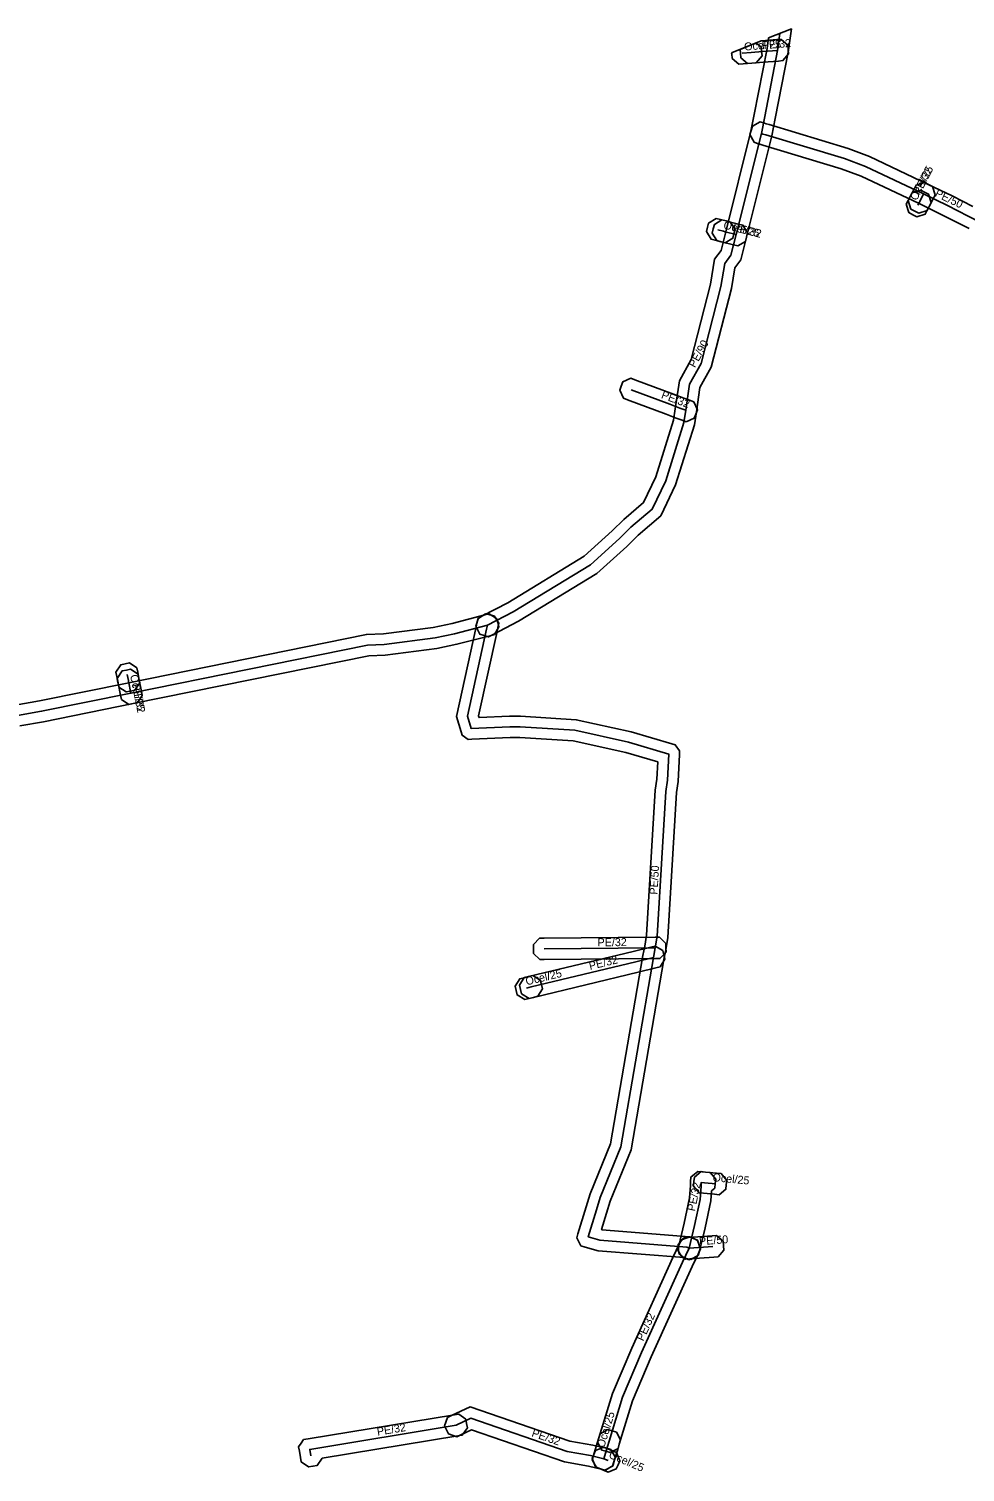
# Model space of a CAD drawing. Extents: x -677728 to -676939, y -1057290 to -1056960.
# Drawn here: x -677137.1 to -677049.4, y -1057099.7 to -1056964.4 of the extents above; entities that cross this region are included whole.
import ezdxf

# ---------------------------------------------------------------- set-up
doc = ezdxf.new("R2010")
doc.units = 0
for name, color, linetype in [('1', 7, 'Continuous'), ('24', 7, 'Continuous'), ('28', 7, 'Continuous'), ('30', 7, 'Continuous')]:
    doc.layers.add(name, color=color, linetype=linetype)

msp = doc.modelspace()

# ---------------------------------------------------------------- linework, layer by layer
at = {"layer": '1'}
for points in [[(-677067.91, -1056966.29), (-677067.77, -1056965.29), (-677065.63, -1056964.44), (-677065.93, -1056966.61), (-677067.15, -1056972.85), (-677067.46, -1056974.46), (-677069.84, -1056983.95), (-677070.38, -1056986.08), (-677070.92, -1056986.83), (-677071.25, -1056988.78), (-677073.15, -1056996.15), (-677074.2, -1056998.05), (-677074.53, -1057000.32), (-677074.71, -1057001.55), (-677076.47, -1057007.15), (-677077.86, -1057010.07), (-677079.98, -1057011.88), (-677081.03, -1057012.93), (-677083.85, -1057015.46), (-677091.2, -1057019.95), (-677093.64, -1057021.22), (-677094.01, -1057021.41), (-677094.8, -1057021.16), (-677094.99, -1057020.79), (-677095.18, -1057020.42), (-677094.93, -1057019.63), (-677094.56, -1057019.44), (-677092.18, -1057018.21), (-677085.05, -1057013.84), (-677082.41, -1057011.47), (-677081.34, -1057010.4), (-677079.48, -1057008.83), (-677078.33, -1057006.41), (-677076.67, -1057001.1), (-677076.51, -1057000.03), (-677076.12, -1056997.41), (-677075.03, -1056995.41), (-677073.21, -1056988.36), (-677072.82, -1056986.03), (-677072.22, -1056985.22), (-677071.78, -1056983.46), (-677069.42, -1056974.02), (-677069.11, -1056972.47)], [(-677070.44, -1056966.36), (-677068.46, -1056965.57), (-677068.43, -1056965.57), (-677067, -1056965.45), (-677066.59, -1056965.42), (-677065.96, -1056965.96), (-677065.92, -1056966.37), (-677065.89, -1056966.78), (-677066.43, -1056967.41), (-677066.84, -1056967.45), (-677068.27, -1056967.56), (-677069.33, -1056967.64), (-677069.75, -1056967.68), (-677070.38, -1056967.14), (-677070.41, -1056966.73)], [(-677071.23, -1056966.68), (-677068.92, -1056965.75), (-677068.45, -1056966.15), (-677068.42, -1056966.57), (-677068.38, -1056966.98), (-677068.92, -1056967.61), (-677069.33, -1056967.64), (-677070.15, -1056967.71), (-677070.56, -1056967.74), (-677071.19, -1056967.21), (-677071.22, -1056966.79)], [(-677052.16, -1056980), (-677052.35, -1056980.37), (-677052.72, -1056981.08), (-677052.91, -1056981.45), (-677053.7, -1056981.7), (-677054.07, -1056981.51), (-677054.44, -1056981.32), (-677054.69, -1056980.53), (-677054.5, -1056980.16), (-677054.13, -1056979.45), (-677053.94, -1056979.08), (-677053.15, -1056978.83), (-677052.78, -1056979.02), (-677052.41, -1056979.21)], [(-677054.87, -1056980.87), (-677054.68, -1056980.51), (-677054.53, -1056980.22), (-677054.5, -1056980.16), (-677054.31, -1056979.79), (-677053.52, -1056979.54), (-677053.15, -1056979.73), (-677052.78, -1056979.92), (-677052.53, -1056980.71), (-677052.72, -1056981.08), (-677052.75, -1056981.14), (-677052.9, -1056981.43), (-677053.09, -1056981.8), (-677053.88, -1056982.05), (-677054.25, -1056981.85), (-677054.62, -1056981.66)], [(-677071.82, -1056984.48), (-677072.22, -1056984.38), (-677072.76, -1056984.25), (-677073.16, -1056984.15), (-677073.59, -1056983.44), (-677073.48, -1056983.03), (-677073.38, -1056982.63), (-677072.67, -1056982.21), (-677072.27, -1056982.31), (-677071.73, -1056982.44), (-677071.33, -1056982.54), (-677070.91, -1056983.25), (-677071.01, -1056983.65), (-677071.11, -1056984.06)], [(-677070.65, -1056984.77), (-677071.06, -1056984.67), (-677072.08, -1056984.42), (-677072.22, -1056984.38), (-677072.62, -1056984.28), (-677073.05, -1056983.57), (-677072.95, -1056983.17), (-677072.84, -1056982.76), (-677072.13, -1056982.34), (-677071.73, -1056982.44), (-677071.59, -1056982.48), (-677070.57, -1056982.73), (-677070.17, -1056982.83), (-677069.74, -1056983.54), (-677069.84, -1056983.95), (-677069.94, -1056984.35)], [(-677075.49, -1057001.26), (-677075.87, -1057001.11), (-677076.42, -1057000.91), (-677077.37, -1057000.55), (-677080.98, -1056999.19), (-677081.37, -1056999.05), (-677081.71, -1056998.29), (-677081.57, -1056997.91), (-677081.42, -1056997.52), (-677080.67, -1056997.18), (-677080.28, -1056997.32), (-677076.66, -1056998.68), (-677075.71, -1056999.04), (-677075.17, -1056999.24), (-677074.78, -1056999.39), (-677074.44, -1057000.14), (-677074.58, -1057000.53), (-677074.73, -1057000.92)], [(-677075.25, -1057079.78), (-677075.62, -1057079.61), (-677075.68, -1057079.58), (-677083.74, -1057078.95), (-677084.95, -1057078.59), (-677085.34, -1057078.47), (-677085.54, -1057078.1), (-677085.74, -1057077.74), (-677085.62, -1057077.34), (-677084.86, -1057074.82), (-677084.48, -1057073.61), (-677082.58, -1057068.91), (-677079.53, -1057051.27), (-677079.36, -1057050.39), (-677079.2, -1057049.36), (-677078.39, -1057035.78), (-677078.22, -1057034.75), (-677078.15, -1057033.13), (-677081.13, -1057032.24), (-677086.06, -1057031.16), (-677091.06, -1057030.83), (-677091.98, -1057030.84), (-677095.56, -1057031.01), (-677095.91, -1057031.02), (-677096.46, -1057030.63), (-677096.57, -1057030.3), (-677097, -1057028.88), (-677095.16, -1057020.48), (-677095.08, -1057020.12), (-677094.99, -1057019.71), (-677094.29, -1057019.26), (-677093.89, -1057019.35), (-677093.48, -1057019.44), (-677093.03, -1057020.14), (-677093.12, -1057020.54), (-677093.2, -1057020.9), (-677094.94, -1057028.8), (-677094.88, -1057028.98), (-677092.04, -1057028.84), (-677091, -1057028.83), (-677085.78, -1057029.18), (-677080.63, -1057030.3), (-677076.83, -1057031.44), (-677076.51, -1057031.54), (-677076.11, -1057032.1), (-677076.12, -1057032.44), (-677076.22, -1057034.95), (-677076.4, -1057036), (-677077.2, -1057049.58), (-677077.39, -1057050.74), (-677077.57, -1057051.63), (-677080.64, -1057069.47), (-677082.6, -1057074.29), (-677082.94, -1057075.4), (-677083.41, -1057076.96), (-677083.38, -1057076.97), (-677075.18, -1057077.62), (-677074.8, -1057077.79), (-677074.42, -1057077.96), (-677074.13, -1057078.74), (-677074.3, -1057079.11), (-677074.47, -1057079.49)], [(-677128.62, -1057026.12), (-677128.7, -1057025.71), (-677128.82, -1057025.12), (-677128.91, -1057024.72), (-677128.45, -1057024.03), (-677128.04, -1057023.95), (-677127.63, -1057023.86), (-677126.94, -1057024.32), (-677126.86, -1057024.73), (-677126.74, -1057025.32), (-677126.66, -1057025.72), (-677127.12, -1057026.41), (-677127.53, -1057026.49), (-677127.93, -1057026.57)], [(-677128.39, -1057027.29), (-677128.47, -1057026.89), (-677128.7, -1057025.74), (-677128.71, -1057025.71), (-677128.79, -1057025.3), (-677128.33, -1057024.61), (-677127.92, -1057024.53), (-677127.52, -1057024.45), (-677126.83, -1057024.91), (-677126.74, -1057025.32), (-677126.74, -1057025.35), (-677126.51, -1057026.49), (-677126.43, -1057026.9), (-677126.89, -1057027.59), (-677127.29, -1057027.67), (-677127.7, -1057027.75)], [(-677077.91, -1057052.32), (-677078.32, -1057052.42), (-677079.97, -1057052.82), (-677089.79, -1057055.19), (-677090.19, -1057055.29), (-677090.9, -1057054.86), (-677090.99, -1057054.45), (-677091.09, -1057054.05), (-677090.66, -1057053.34), (-677090.26, -1057053.25), (-677080.44, -1057050.88), (-677078.79, -1057050.48), (-677078.38, -1057050.38), (-677077.68, -1057050.81), (-677077.58, -1057051.22), (-677077.48, -1057051.62)], [(-677089.21, -1057049.66), (-677088.8, -1057049.66), (-677078.39, -1057049.56), (-677077.97, -1057049.56), (-677077.38, -1057050.14), (-677077.38, -1057050.55), (-677077.37, -1057050.97), (-677077.95, -1057051.56), (-677078.37, -1057051.56), (-677088.78, -1057051.66), (-677089.19, -1057051.66), (-677089.78, -1057051.08), (-677089.79, -1057050.66), (-677089.79, -1057050.25)], [(-677089.38, -1057055.09), (-677089.79, -1057055.19), (-677090.21, -1057055.29), (-677090.61, -1057055.39), (-677091.32, -1057054.96), (-677091.41, -1057054.55), (-677091.51, -1057054.15), (-677091.08, -1057053.45), (-677090.67, -1057053.35), (-677090.26, -1057053.25), (-677089.85, -1057053.15), (-677089.15, -1057053.58), (-677089.05, -1057053.99), (-677088.95, -1057054.39)], [(-677072.8, -1057073.06), (-677073.12, -1057073.33), (-677073.19, -1057074.26), (-677073.72, -1057076.79), (-677074.24, -1057078.93), (-677074.33, -1057079.34), (-677075.04, -1057079.77), (-677075.44, -1057079.67), (-677075.85, -1057079.58), (-677076.28, -1057078.87), (-677076.18, -1057078.47), (-677075.68, -1057076.35), (-677075.17, -1057073.98), (-677075.09, -1057072.82), (-677075.07, -1057072.46), (-677075.04, -1057072.04), (-677074.72, -1057071.77), (-677074.4, -1057071.5), (-677073.98, -1057071.53), (-677073.67, -1057071.56), (-677073.25, -1057071.6), (-677072.72, -1057072.24), (-677072.76, -1057072.65)], [(-677074.08, -1057071.52), (-677073.67, -1057071.56), (-677072.63, -1057071.66), (-677072.22, -1057071.7), (-677071.69, -1057072.34), (-677071.73, -1057072.75), (-677071.77, -1057073.17), (-677072.41, -1057073.69), (-677072.82, -1057073.65), (-677073.85, -1057073.55), (-677074.27, -1057073.52), (-677074.8, -1057072.88), (-677074.76, -1057072.46), (-677074.72, -1057072.05)], [(-677074.13, -1057078.76), (-677074.31, -1057079.13), (-677074.92, -1057080.42), (-677078.75, -1057088.88), (-677080.51, -1057093), (-677081.75, -1057097.07), (-677081.87, -1057097.46), (-677082.6, -1057097.85), (-677083, -1057097.73), (-677083.4, -1057097.61), (-677083.78, -1057096.88), (-677083.66, -1057096.48), (-677082.39, -1057092.32), (-677080.59, -1057088.08), (-677076.74, -1057079.58), (-677076.11, -1057078.27), (-677075.93, -1057077.9), (-677075.15, -1057077.62), (-677074.78, -1057077.8), (-677074.41, -1057077.98)], [(-677075.7, -1057077.73), (-677075.28, -1057077.7), (-677073.05, -1057077.54), (-677072.64, -1057077.51), (-677072.01, -1057078.05), (-677071.98, -1057078.47), (-677071.95, -1057078.88), (-677072.49, -1057079.51), (-677072.91, -1057079.54), (-677075.14, -1057079.7), (-677075.55, -1057079.73), (-677076.18, -1057079.19), (-677076.21, -1057078.77), (-677076.24, -1057078.36)], [(-677083.04, -1057099.49), (-677083.44, -1057099.39), (-677084.64, -1057099.11), (-677086.88, -1057098.72), (-677095.6, -1057095.72), (-677096.6, -1057096.2), (-677096.98, -1057096.38), (-677097.76, -1057096.1), (-677097.94, -1057095.72), (-677098.12, -1057095.35), (-677097.84, -1057094.57), (-677097.46, -1057094.39), (-677095.72, -1057093.56), (-677086.38, -1057096.78), (-677084.24, -1057097.15), (-677082.98, -1057097.45), (-677082.58, -1057097.54), (-677082.14, -1057098.25), (-677082.24, -1057098.65), (-677082.33, -1057099.05)], [(-677096.87, -1057096.28), (-677109.58, -1057098.37), (-677110.04, -1057099.05), (-677110.45, -1057099.13), (-677110.86, -1057099.2), (-677111.54, -1057098.73), (-677111.61, -1057098.32), (-677111.72, -1057097.73), (-677111.8, -1057097.32), (-677111.56, -1057096.97), (-677111.32, -1057096.63), (-677110.9, -1057096.56), (-677097.2, -1057094.31), (-677096.79, -1057094.24), (-677096.12, -1057094.72), (-677096.05, -1057095.13), (-677095.98, -1057095.54), (-677096.46, -1057096.21)], [(-677081.63, -1057096.67), (-677081.75, -1057097.07), (-677081.9, -1057097.57), (-677082.25, -1057098.71), (-677082.38, -1057099.11), (-677083.11, -1057099.5), (-677083.5, -1057099.38), (-677083.9, -1057099.26), (-677084.29, -1057098.52), (-677084.17, -1057098.13), (-677083.82, -1057096.98), (-677083.66, -1057096.48), (-677083.54, -1057096.09), (-677082.81, -1057095.7), (-677082.41, -1057095.82), (-677082.02, -1057095.94)], [(-677083.2, -1057097.34), (-677082.82, -1057097.5), (-677082.4, -1057097.68), (-677082.02, -1057097.84), (-677081.71, -1057098.61), (-677081.87, -1057098.99), (-677082.03, -1057099.37), (-677082.8, -1057099.68), (-677083.18, -1057099.52), (-677083.6, -1057099.34), (-677083.98, -1057099.18), (-677084.29, -1057098.41), (-677084.13, -1057098.03), (-677083.97, -1057097.65)]]:
    msp.add_lwpolyline(points, close=True, dxfattribs=at)
for points in [[(-677048.98, -1056983.15), (-677049.53, -1056982.87), (-677051.46, -1056981.89), (-677053.67, -1056980.81), (-677059.08, -1056978.25), (-677060.96, -1056977.55), (-677068.3, -1056975.33), (-677068.58, -1056975.24), (-677068.73, -1056975.2), (-677069.13, -1056975.07), (-677069.52, -1056974.34), (-677069.4, -1056973.95), (-677069.28, -1056973.55), (-677068.54, -1056973.16), (-677068.15, -1056973.28), (-677067.99, -1056973.33), (-677067.72, -1056973.41), (-677060.32, -1056975.65), (-677058.3, -1056976.41), (-677052.81, -1056979.01), (-677050.56, -1056980.09), (-677048.63, -1056981.09)], [(-677138.33, -1057027.8), (-677136.05, -1057027.4), (-677127.69, -1057025.71), (-677105.43, -1057021.18), (-677103.85, -1057021.14), (-677099.17, -1057020.52), (-677097.42, -1057020.17), (-677094.35, -1057019.36), (-677093.95, -1057019.26), (-677093.24, -1057019.68), (-677093.13, -1057020.08), (-677093.03, -1057020.48), (-677093.45, -1057021.19), (-677093.85, -1057021.3), (-677096.96, -1057022.11), (-677098.84, -1057022.5), (-677103.69, -1057023.14), (-677105.21, -1057023.18), (-677127.29, -1057027.67), (-677135.67, -1057029.36), (-677137.91, -1057029.76)]]:
    msp.add_lwpolyline(points, dxfattribs=at)
at = {"layer": '24'}
for points in [[(-677094.1, -1057020.33), (-677091.69, -1057019.08), (-677084.45, -1057014.65), (-677081.72, -1057012.2), (-677080.66, -1057011.14), (-677078.67, -1057009.45), (-677077.4, -1057006.78), (-677075.69, -1057001.33), (-677075.52, -1057000.18), (-677075.16, -1056997.73), (-677074.09, -1056995.78), (-677072.23, -1056988.57), (-677071.87, -1056986.43), (-677071.3, -1056985.65), (-677070.81, -1056983.7), (-677068.44, -1056974.24), (-677068.13, -1056972.66), (-677066.92, -1056966.45), (-677066.7, -1056964.87)], [(-677069.41, -1056966.65), (-677070.23, -1056966.71)], [(-677066.92, -1056966.45), (-677068.35, -1056966.56), (-677069.41, -1056966.65)], [(-677041.42, -1056992.81), (-677042.77, -1056990.32), (-677043.07, -1056989.79), (-677045.77, -1056985.19), (-677047.27, -1056983.17), (-677048.46, -1056982.29), (-677049.08, -1056981.98), (-677051.01, -1056980.99), (-677053.24, -1056979.91), (-677058.69, -1056977.33), (-677060.64, -1056976.6), (-677068.01, -1056974.37), (-677068.29, -1056974.29), (-677068.44, -1056974.24)], [(-677053.24, -1056979.91), (-677053.61, -1056980.62)], [(-677053.79, -1056980.97), (-677053.64, -1056980.68), (-677053.61, -1056980.62)], [(-677071.98, -1056983.41), (-677072.52, -1056983.28)], [(-677070.81, -1056983.7), (-677071.83, -1056983.45), (-677071.98, -1056983.41)], [(-677138.12, -1057028.78), (-677135.86, -1057028.38), (-677127.49, -1057026.69), (-677105.32, -1057022.18), (-677103.77, -1057022.14), (-677099.01, -1057021.51), (-677097.19, -1057021.14), (-677094.1, -1057020.33)], [(-677075.21, -1057078.7), (-677075.43, -1057078.6), (-677083.56, -1057077.96), (-677084.66, -1057077.63), (-677083.9, -1057075.11), (-677083.54, -1057073.95), (-677081.61, -1057069.19), (-677078.55, -1057051.45), (-677078.38, -1057050.56), (-677078.2, -1057049.47), (-677077.39, -1057035.89), (-677077.22, -1057034.85), (-677077.12, -1057032.4), (-677080.88, -1057031.27), (-677085.92, -1057030.17), (-677091.03, -1057029.83), (-677092.01, -1057029.84), (-677095.61, -1057030.01), (-677095.97, -1057028.84), (-677094.18, -1057020.69), (-677094.1, -1057020.33)], [(-677127.72, -1057025.51), (-677127.84, -1057024.93)], [(-677127.49, -1057026.69), (-677127.72, -1057025.55), (-677127.72, -1057025.51)], [(-677088.79, -1057050.66), (-677078.38, -1057050.56)], [(-677078.55, -1057051.45), (-677080.2, -1057051.85), (-677090.02, -1057054.22)], [(-677090.02, -1057054.22), (-677090.44, -1057054.32)], [(-677073.76, -1057072.56), (-677074.07, -1057072.53), (-677074.09, -1057072.89), (-677074.18, -1057074.12), (-677074.7, -1057076.57), (-677075.21, -1057078.7)], [(-677073.76, -1057072.56), (-677072.72, -1057072.66)], [(-677075.21, -1057078.7), (-677075.83, -1057080), (-677079.67, -1057088.48), (-677081.45, -1057092.66), (-677082.71, -1057096.78)], [(-677075.21, -1057078.7), (-677072.98, -1057078.54)], [(-677097.04, -1057095.29), (-677110.74, -1057097.55), (-677110.63, -1057098.14)], [(-677083.21, -1057098.42), (-677084.44, -1057098.13), (-677086.63, -1057097.75), (-677095.66, -1057094.64), (-677097.04, -1057095.29)], [(-677082.71, -1057096.78), (-677082.86, -1057097.27), (-677083.21, -1057098.42)], [(-677083.21, -1057098.42), (-677082.79, -1057098.6)]]:
    msp.add_lwpolyline(points, dxfattribs=at)
at = {"layer": '28'}
msp.add_lwpolyline([(-677075.52, -1057000.18), (-677076.07, -1056999.97), (-677077.02, -1056999.62), (-677080.63, -1056998.26)], dxfattribs=at)

# ---------------------------------------------------------------- texts
at = {"layer": '30'}
for s, rotation, p in [('Ocel/25', 4.5655, (-677070.02, -1056966.48)), ('PE/32', 4.5245, (-677068.37, -1056966.35)), ('Ocel/25', 62.5009, (-677053.9, -1056980.59)), ('PE/32', 62.6018, (-677053.62, -1056980.07)), ('PE/50', 334.1589, (-677052.25, -1056980.09)), ('Ocel/25', 345.9387, (-677072.05, -1056983.14)), ('PE/32', 345.9374, (-677071.19, -1056983.36)), ('PE/90', 61.258, (-677074.66, -1056996.25)), ('PE/32', 339.3884, (-677077.88, -1056999.02)), ('Ocel/25', 281.3474, (-677127.58, -1057025.02)), ('PE/32', 281.2906, (-677127.41, -1057025.9)), ('PE/50', 86.5868, (-677078.18, -1057045.58)), ('PE/32', 0.5063, (-677083.78, -1057050.41)), ('PE/32', 13.5712, (-677084.49, -1057052.63)), ('Ocel/25', 13.5526, (-677090.43, -1057054.07)), ('Ocel/25', 354.5414, (-677073.04, -1057072.41)), ('PE/32', 78.0171, (-677074.67, -1057075.28)), ('PE/50', 4.1039, (-677074.25, -1057078.42)), ('PE/32', 65.6375, (-677079.5, -1057087.46)), ('Ocel/25', 73.0028, (-677083.17, -1057097.45)), ('PE/32', 9.343, (-677104.39, -1057096.27)), ('PE/32', 340.9959, (-677090.02, -1057096.31)), ('Ocel/25', 336.8507, (-677082.8, -1057098.31))]:
    msp.add_text(s, height=0.75, rotation=rotation, dxfattribs=at).set_placement(p)

doc.saveas('drawing.dxf')
